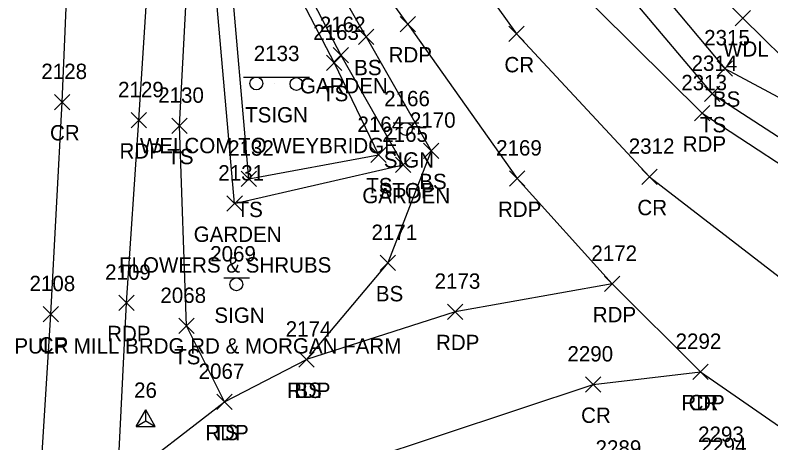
# Model space of a CAD drawing. Extents: x 1461855 to 1464118, y 556196 to 557441.
# Drawn here: x 1461940.8 to 1462039.2, y 556448.6 to 556504.3 of the extents above; entities that cross this region are included whole.
import ezdxf

# ---------------------------------------------------------------- set-up
doc = ezdxf.new("R2010")
doc.units = 0
for name, color, linetype in [('C_I', 7, 'Continuous'), ('CPSM', 7, 'Continuous'), ('L_A', 7, 'Continuous'), ('L_C', 7, 'Continuous'), ('L_I', 7, 'Continuous'), ('L_TIC', 7, 'Continuous'), ('LAPB', 7, 'Continuous'), ('LAWA', 7, 'Continuous'), ('LELB', 7, 'Continuous'), ('P_A', 7, 'Continuous'), ('P_I', 7, 'Continuous'), ('P_TIC', 7, 'Continuous'), ('PET', 7, 'Continuous'), ('PRC', 7, 'Continuous'), ('S_A', 7, 'Continuous'), ('S_C', 7, 'Continuous'), ('S_I', 7, 'Continuous'), ('SSGN', 7, 'Continuous')]:
    doc.layers.add(name, color=color, linetype=linetype)

msp = doc.modelspace()

# ---------------------------------------------------------------- linework, layer by layer
at = {"layer": 'CPSM'}
for p, q in [((1461956.604, 556450.758), (1461957.854, 556452.923)), ((1461959.104, 556450.758), (1461957.854, 556452.923)), ((1461957.854, 556451.479), (1461957.854, 556452.923)), ((1461956.604, 556450.758), (1461957.854, 556451.479)), ((1461957.854, 556451.479), (1461957.854, 556451.479)), ((1461957.854, 556451.479), (1461959.104, 556450.758)), ((1461956.604, 556450.758), (1461959.104, 556450.758))]:
    msp.add_line(p, q, dxfattribs=at)
at = {"layer": 'L_TIC'}
for points in [[(1462034.594, 556502.943), (1462036.594, 556504.943)], [(1462036.594, 556502.943), (1462034.594, 556504.943)], [(1461985.545, 556500.514), (1461987.545, 556502.514)], [(1461987.545, 556500.514), (1461985.545, 556502.514)], [(1461982.258, 556498.141), (1461984.258, 556500.141)], [(1461984.258, 556498.141), (1461982.258, 556500.141)], [(1461981.392, 556497.113), (1461983.392, 556499.113)], [(1461983.392, 556497.113), (1461981.392, 556499.113)], [(1462032.248, 556496.405), (1462034.248, 556498.405)], [(1462034.248, 556496.405), (1462032.248, 556498.405)], [(1462030.601, 556493.072), (1462032.601, 556495.072)], [(1462032.601, 556493.072), (1462030.601, 556495.072)], [(1461961.252, 556488.921), (1461963.252, 556490.921)], [(1461963.252, 556488.921), (1461961.252, 556490.921)], [(1461994.024, 556485.675), (1461996.024, 556487.675)], [(1461996.024, 556485.675), (1461994.024, 556487.675)], [(1461987.155, 556485.125), (1461989.155, 556487.125)], [(1461989.155, 556485.125), (1461987.155, 556487.125)], [(1461987.155, 556485.125), (1461989.155, 556487.125)], [(1461989.155, 556485.125), (1461987.155, 556487.125)], [(1461990.381, 556483.83), (1461992.381, 556485.83)], [(1461992.381, 556483.83), (1461990.381, 556485.83)], [(1461990.381, 556483.83), (1461992.381, 556485.83)], [(1461992.381, 556483.83), (1461990.381, 556485.83)], [(1461970.273, 556482.028), (1461972.273, 556484.028)], [(1461972.273, 556482.028), (1461970.273, 556484.028)], [(1461970.273, 556482.028), (1461972.273, 556484.028)], [(1461972.273, 556482.028), (1461970.273, 556484.028)], [(1461968.431, 556478.795), (1461970.431, 556480.795)], [(1461970.431, 556478.795), (1461968.431, 556480.795)], [(1461968.431, 556478.795), (1461970.431, 556480.795)], [(1461970.431, 556478.795), (1461968.431, 556480.795)], [(1461988.371, 556471.049), (1461990.371, 556473.049)], [(1461990.371, 556471.049), (1461988.371, 556473.049)], [(1461962.145, 556462.844), (1461964.145, 556464.844)], [(1461964.145, 556462.844), (1461962.145, 556464.844)], [(1461977.771, 556458.457), (1461979.771, 556460.457)], [(1461979.771, 556458.457), (1461977.771, 556460.457)], [(1461967.123, 556452.952), (1461969.123, 556454.952)], [(1461969.123, 556452.952), (1461967.123, 556454.952)]]:
    msp.add_lwpolyline(points, dxfattribs=at)
at = {"layer": 'LAPB'}
for points in [[(1461969.431, 556479.795), (1461966.325, 556514.879), (1461974.149, 556516.63), (1461983.258, 556499.141), (1461991.381, 556484.83)], [(1461969.431, 556479.795), (1461991.381, 556484.83)]]:
    msp.add_lwpolyline(points, dxfattribs=at)
at = {"layer": 'LAWA'}
msp.add_lwpolyline([(1461966.99, 556643.855), (1461970.758, 556630.806), (1461974.775, 556610.383), (1461978.018, 556594.214), (1461979.63, 556591.534), (1461980.916, 556588.073), (1461980.911, 556585.996), (1461997.991, 556566.696), (1461991.485, 556562.204), (1461998.233, 556546.822), (1462003.925, 556533.351), (1462020.908, 556518.859), (1462035.594, 556503.943), (1462051.308, 556488.469), (1462071.482, 556482.443), (1462073.826, 556488.172), (1462091.483, 556509.713), (1462111.543, 556518.091), (1462114.944, 556522.402), (1462105.835, 556530.217)], dxfattribs=at)
at = {"layer": 'LELB'}
for points in [[(1461963.705, 556606.006), (1461972.105, 556589.426), (1461974.569, 556579.664), (1461977.523, 556575.662), (1461983.683, 556561.117), (1461995.205, 556544.635), (1462001.849, 556531.766), (1462015.715, 556512.95), (1462031.601, 556494.072), (1462048.722, 556482.954), (1462068.844, 556473.098), (1462085.604, 556465.871), (1462095.004, 556462.84), (1462104.945, 556460.104), (1462122.08, 556455.999), (1462130.643, 556454.493), (1462134.696, 556456.084), (1462145.09, 556459.049)], [(1462003.925, 556533.351), (1462018.122, 556515.464), (1462033.248, 556497.405), (1462071.175, 556477.093), (1462086.801, 556469.546), (1462096.393, 556465.563), (1462108.839, 556467.675), (1462124.65, 556460.477), (1462134.696, 556456.084)], [(1461968.123, 556453.952), (1461963.145, 556463.844), (1461962.252, 556489.921), (1461963.996, 556522.718)], [(1461986.545, 556501.514), (1461975.308, 556521.219)], [(1461971.273, 556483.028), (1461968.805, 556511.463), (1461973.525, 556515.172), (1461982.392, 556498.113), (1461988.155, 556486.125)], [(1461986.545, 556501.514), (1461995.024, 556486.675), (1461989.371, 556472.049), (1461978.771, 556459.457)], [(1461971.273, 556483.028), (1461988.155, 556486.125)]]:
    msp.add_lwpolyline(points, dxfattribs=at)
at = {"layer": 'P_TIC'}
for points in [[(1461990.983, 556502.178), (1461992.983, 556504.178)], [(1461992.983, 556502.178), (1461990.983, 556504.178)], [(1462005.117, 556500.89), (1462007.117, 556502.89)], [(1462007.117, 556500.89), (1462005.117, 556502.89)], [(1461945.96, 556492.016), (1461947.96, 556494.016)], [(1461947.96, 556492.016), (1461945.96, 556494.016)], [(1462029.273, 556490.558), (1462031.273, 556492.558)], [(1462031.273, 556490.558), (1462029.273, 556492.558)], [(1461955.954, 556489.651), (1461957.954, 556491.651)], [(1461957.954, 556489.651), (1461955.954, 556491.651)], [(1462005.217, 556482.047), (1462007.217, 556484.047)], [(1462007.217, 556482.047), (1462005.217, 556484.047)], [(1462022.427, 556482.274), (1462024.427, 556484.274)], [(1462024.427, 556482.274), (1462022.427, 556484.274)], [(1462017.561, 556468.328), (1462019.561, 556470.328)], [(1462019.561, 556468.328), (1462017.561, 556470.328)], [(1462017.561, 556468.328), (1462019.561, 556470.328)], [(1462019.561, 556468.328), (1462017.561, 556470.328)], [(1461954.345, 556465.861), (1461956.345, 556467.861)], [(1461956.345, 556465.861), (1461954.345, 556467.861)], [(1461944.493, 556464.379), (1461946.493, 556466.379)], [(1461946.493, 556464.379), (1461944.493, 556466.379)], [(1461997.156, 556464.691), (1461999.156, 556466.691)], [(1461999.156, 556464.691), (1461997.156, 556466.691)], [(1461977.771, 556458.457), (1461979.771, 556460.457)], [(1461979.771, 556458.457), (1461977.771, 556460.457)], [(1461977.771, 556458.457), (1461979.771, 556460.457)], [(1461979.771, 556458.457), (1461977.771, 556460.457)], [(1462029.094, 556456.862), (1462031.094, 556458.862)], [(1462031.094, 556456.862), (1462029.094, 556458.862)], [(1462029.094, 556456.862), (1462031.094, 556458.862)], [(1462031.094, 556456.862), (1462029.094, 556458.862)], [(1462015.097, 556455.217), (1462017.097, 556457.217)], [(1462017.097, 556455.217), (1462015.097, 556457.217)], [(1461967.123, 556452.952), (1461969.123, 556454.952)], [(1461969.123, 556452.952), (1461967.123, 556454.952)]]:
    msp.add_lwpolyline(points, dxfattribs=at)
at = {"layer": 'PET'}
for points in [[(1461941.434, 556640.486), (1461960.909, 556600.588), (1461969.587, 556584.051), (1461984.634, 556553.378), (1461998.6, 556528.817), (1462012.322, 556509.397), (1462030.273, 556491.558), (1462047.25, 556480.456), (1462067.715, 556469.893), (1462084.829, 556462.245), (1462093.335, 556458.861), (1462103.997, 556455.555), (1462121.999, 556451.359), (1462134.064, 556450.116), (1462148.835, 556449.192)], [(1461991.983, 556503.178), (1461976.486, 556524.734)], [(1461956.954, 556490.651), (1461958.976, 556522.338)], [(1461991.983, 556503.178), (1462006.217, 556483.047), (1462018.561, 556469.328), (1462030.094, 556457.862), (1462048.811, 556444.893), (1462057.177, 556443.273), (1462083.113, 556436.833), (1462114.96, 556430.915), (1462132.36, 556428.115), (1462140.707, 556427.525), (1462147.35, 556427.105), (1462147.933, 556438.199), (1462148.835, 556449.192)], [(1461935.994, 556304.706), (1461941.55, 556343.697), (1461948.694, 556384.516), (1461950.446, 556390.309), (1461951.969, 556426.622), (1461954.173, 556443.192), (1461955.345, 556466.861), (1461956.954, 556490.651)], [(1462018.561, 556469.328), (1461998.156, 556465.691), (1461978.771, 556459.457)], [(1461954.173, 556443.192), (1461968.123, 556453.952), (1461978.771, 556459.457)]]:
    msp.add_lwpolyline(points, dxfattribs=at)
at = {"layer": 'PRC'}
for points in [[(1461925.455, 556305.981), (1461931.482, 556345.963), (1461937.931, 556386.439), (1461943.124, 556427.083), (1461945.493, 556465.379), (1461946.96, 556493.016), (1461948.287, 556523.837), (1461949.597, 556552.436), (1461949.092, 556575.708), (1461945.132, 556594.535), (1461941.155, 556612.685), (1461941.736, 556618.093), (1461960.038, 556581.267), (1461976.525, 556548.035), (1461990.309, 556523.955), (1462006.117, 556501.89), (1462023.427, 556483.274), (1462041.849, 556469.086), (1462061.758, 556457.443), (1462082.723, 556450.203), (1462107.816, 556443.977), (1462129.573, 556440.387), (1462147.933, 556438.199)], [(1461951.969, 556426.622), (1461963.807, 556434.71), (1461976.359, 556443.012), (1462016.097, 556456.217), (1462030.094, 556457.862)]]:
    msp.add_lwpolyline(points, dxfattribs=at)
at = {"layer": 'SSGN'}
for p, q in [((1461970.594, 556496.274), (1461979.191, 556496.274)), ((1461974.616, 556495.37), (1461974.616, 556495.37)), ((1461990.063, 556490.326), (1461993.396, 556490.326)), ((1461991.709, 556489.492), (1461991.709, 556489.492)), ((1461968.009, 556470.099), (1461971.342, 556470.099)), ((1461969.656, 556469.266), (1461969.656, 556469.266))]:
    msp.add_line(p, q, dxfattribs=at)
for centre in [(1461972.255, 556495.441), (1461977.47, 556495.37), (1461991.709, 556489.492), (1461969.656, 556469.266)]:
    msp.add_circle(centre, 0.833, dxfattribs=at)

# ---------------------------------------------------------------- texts
at = {"layer": 'C_I'}
msp.add_text('26', height=2, dxfattribs=at).set_placement((1461956.334, 556454.479))
at = {"layer": 'L_A'}
for s, p in [('WDL', (1462033.012, 556498.943)), ('BS', (1461984.986, 556496.514)), ('GARDEN', (1461977.927, 556494.141)), ('TS', (1461980.802, 556493.113)), ('BS', (1462031.689, 556492.405)), ('TS', (1462030.01, 556489.072)), ('TS', (1461960.662, 556484.921)), ('BS', (1461993.465, 556481.675)), ('TS', (1461986.564, 556481.125)), ('TS', (1461986.564, 556481.125)), ('GARDEN', (1461986.05, 556479.83)), ('GARDEN', (1461986.05, 556479.83)), ('TS', (1461969.682, 556478.028)), ('TS', (1461969.682, 556478.028)), ('GARDEN', (1461964.1, 556474.795)), ('GARDEN', (1461964.1, 556474.795)), ('BS', (1461987.812, 556467.049)), ('TS', (1461961.554, 556458.844)), ('BS', (1461977.212, 556454.457)), ('TS', (1461966.533, 556448.952))]:
    msp.add_text(s, height=2, dxfattribs=at).set_placement(p)
at = {"layer": 'L_C'}
msp.add_text('FLOWERS & SHRUBS', height=2, dxfattribs=at).set_placement((1461954.376, 556470.795))
msp.add_text('FLOWERS & SHRUBS', height=2, dxfattribs=at).set_placement((1461954.376, 556470.795))
at = {"layer": 'L_I'}
for s, p in [('2162', (1461980.517, 556502.141)), ('2163', (1461979.652, 556501.113)), ('2315', (1462030.555, 556500.405)), ('2314', (1462028.908, 556497.072)), ('2130', (1461959.473, 556492.921)), ('2170', (1461992.245, 556489.675)), ('2164', (1461985.415, 556489.125)), ('2164', (1461985.415, 556489.125)), ('2165', (1461988.64, 556487.83)), ('2165', (1461988.64, 556487.83)), ('2132', (1461968.58, 556486.028)), ('2132', (1461968.58, 556486.028)), ('2131', (1461967.305, 556482.795)), ('2131', (1461967.305, 556482.795)), ('2171', (1461987.245, 556475.049)), ('2068', (1461959.759, 556466.844)), ('2174', (1461976.078, 556462.457)), ('2067', (1461964.738, 556456.952)), ('2294', (1462030.109, 556447.277))]:
    msp.add_text(s, height=2, dxfattribs=at).set_placement(p)
at = {"layer": 'P_A'}
for s, p in [('RDP', (1461989.471, 556498.178)), ('CR', (1462004.55, 556496.89)), ('CR', (1461945.393, 556488.016)), ('RDP', (1462027.761, 556486.558)), ('RDP', (1461954.442, 556485.651)), ('RDP', (1462003.705, 556478.047)), ('CR', (1462021.86, 556478.274)), ('RDP', (1462016.049, 556464.328)), ('RDP', (1462016.049, 556464.328)), ('RDP', (1461952.833, 556461.861)), ('CR', (1461943.926, 556460.379)), ('RDP', (1461995.644, 556460.691)), ('RDP', (1461976.26, 556454.457)), ('RDP', (1461976.26, 556454.457)), ('RDP', (1462027.582, 556452.862)), ('CR', (1462028.527, 556452.862)), ('CR', (1462014.53, 556451.217)), ('RDP', (1461965.612, 556448.952))]:
    msp.add_text(s, height=2, dxfattribs=at).set_placement(p)
at = {"layer": 'P_I'}
for s, p in [('2128', (1461944.267, 556496.016)), ('2313', (1462027.58, 556494.558)), ('2129', (1461954.253, 556493.651)), ('2169', (1462003.469, 556486.047)), ('2312', (1462020.734, 556486.274)), ('2172', (1462015.868, 556472.328)), ('2172', (1462015.868, 556472.328)), ('2109', (1461952.565, 556469.861)), ('2173', (1461995.463, 556468.691)), ('2108', (1461942.722, 556468.379)), ('2174', (1461976.078, 556462.457)), ('2174', (1461976.078, 556462.457)), ('2292', (1462026.834, 556460.862)), ('2292', (1462026.834, 556460.862)), ('2290', (1462012.751, 556459.217)), ('2067', (1461964.738, 556456.952)), ('2293', (1462029.761, 556448.734)), ('2289', (1462016.415, 556446.946))]:
    msp.add_text(s, height=2, dxfattribs=at).set_placement(p)
at = {"layer": 'S_A'}
for s, p in [('TSIGN', (1461970.792, 556490.353)), ('SIGN', (1461988.847, 556484.472)), ('SIGN', (1461966.794, 556464.246))]:
    msp.add_text(s, height=2, dxfattribs=at).set_placement(p)
at = {"layer": 'S_C'}
for s, p in [('WELCOM TO WEYBRIDGE', (1461957.099, 556486.353)), ('STOP', (1461988.17, 556480.472)), ('PULP MILL BRDG RD & MORGAN FARM', (1461940.754, 556460.246))]:
    msp.add_text(s, height=2, dxfattribs=at).set_placement(p)
at = {"layer": 'S_I'}
for s, p in [('2133', (1461971.918, 556498.353)), ('2166', (1461988.895, 556492.472)), ('2069', (1461966.243, 556472.246))]:
    msp.add_text(s, height=2, dxfattribs=at).set_placement(p)

doc.saveas('drawing.dxf')
